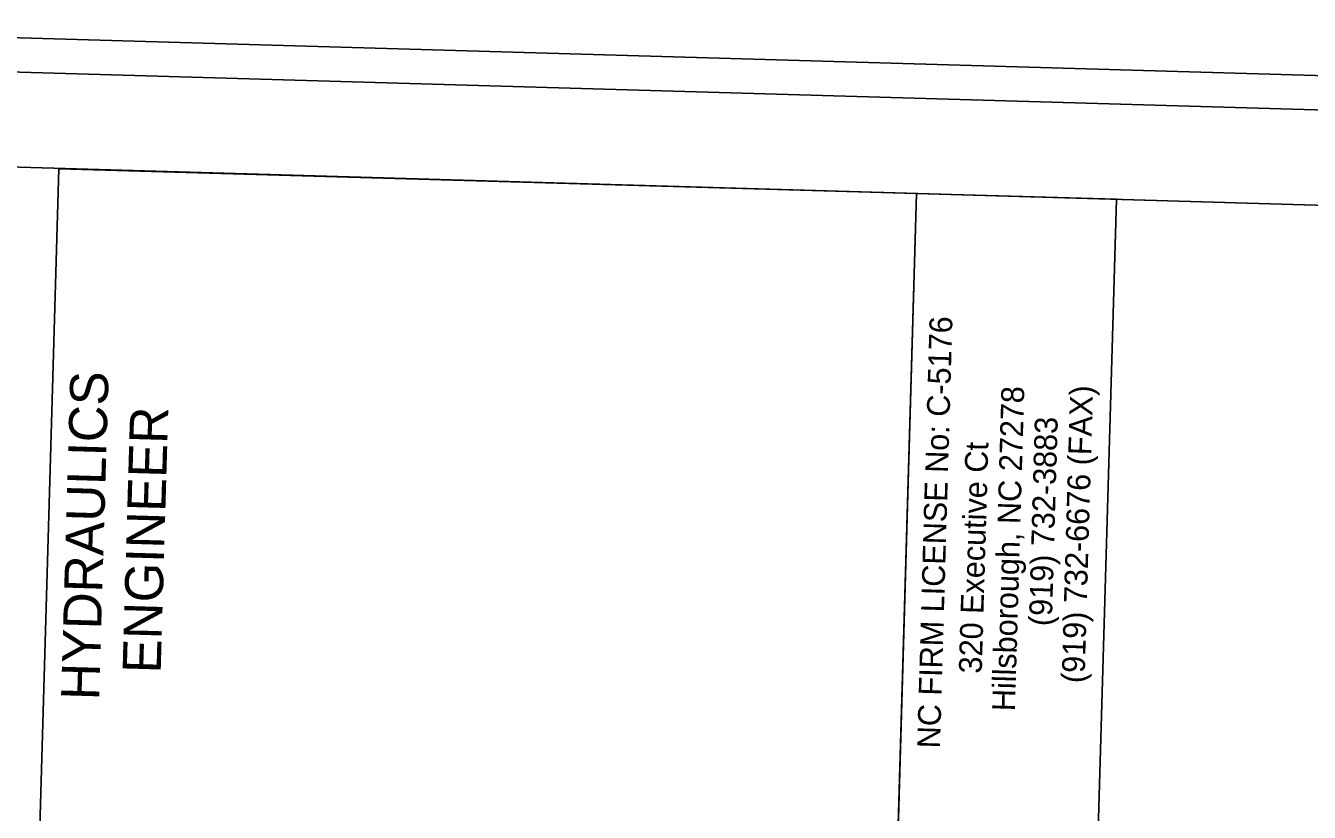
# Model space of a CAD drawing. Extents: x 2096987 to 2098130, y 681809 to 686842.
# Drawn here: x 2097090.9 to 2097259.2, y 686739.3 to 686842.4 of the extents above; entities that cross this region are included whole.
import ezdxf

# ---------------------------------------------------------------- set-up
doc = ezdxf.new("R2010")
doc.units = 0
for name, color, linetype in [('Sheet Block Title CELL', 7, 'Continuous'), ('Sheet Plan CELL', 7, 'Continuous'), ('Sheet Plot Border Inside CELL', 7, 'Continuous'), ('Sheet Plot Border Outside CELL', 7, 'Continuous')]:
    doc.layers.add(name, color=color, linetype=linetype)

msp = doc.modelspace()

# ---------------------------------------------------------------- linework, layer by layer
at = {"layer": 'Sheet Block Title CELL'}
msp.add_lwpolyline([(2097201.88, 686620.47), (2097207.7, 686820.45), (2097233.94, 686819.68), (2097228.13, 686619.71)], close=True, dxfattribs=at)
at = {"layer": 'Sheet Plan CELL'}
for points in [[(2097057.71, 686824.81), (2097014.12, 685325.41), (2098063.68, 685294.9), (2098107.27, 686794.27)], [(2097092.35, 686723.74), (2097095.24, 686823.68), (2097207.71, 686820.43), (2097204.82, 686720.47)], [(2098063.68, 685294.9), (2097014.15, 685325.38), (2097051.88, 686624.82), (2097201.88, 686620.47), (2097207.71, 686820.43), (2098107.27, 686794.27)]]:
    msp.add_lwpolyline(points, close=True, dxfattribs=at)
at = {"layer": 'Sheet Plot Border Inside CELL'}
msp.add_lwpolyline([(2098061.73, 685141.4), (2098110.13, 686806.68), (2097055.59, 686837.35), (2097007.18, 685172.06)], close=True, dxfattribs=at)
at = {"layer": 'Sheet Plot Border Outside CELL'}
msp.add_lwpolyline([(2098081.34, 685127.82), (2098130.26, 686810.61), (2097035.73, 686842.43), (2096986.81, 685159.64)], close=True, dxfattribs=at)

# ---------------------------------------------------------------- texts
at = {"layer": 'Sheet Block Title CELL'}
for s, p in [('NC FIRM LICENSE No: C-5176', (2097210.78, 686747.68)), ('Hillsborough, NC 27278', (2097220.61, 686752.55)), ('(919) 732-6676 (FAX)', (2097229.73, 686756.23)), ('(919) 732-3883', (2097225.44, 686763.7)), ('320 Executive Ct', (2097216.25, 686757.49))]:
    msp.add_text(s, height=3.0009, rotation=88.3348, dxfattribs=at).set_placement(p)
at = {"layer": 'Sheet Plan CELL'}
for s, p in [('HYDRAULICS', (2097100.51, 686753.98)), ('ENGINEER', (2097108.58, 686757.5))]:
    msp.add_text(s, height=5, rotation=88.3348, dxfattribs=at).set_placement(p)

doc.saveas('drawing.dxf')
